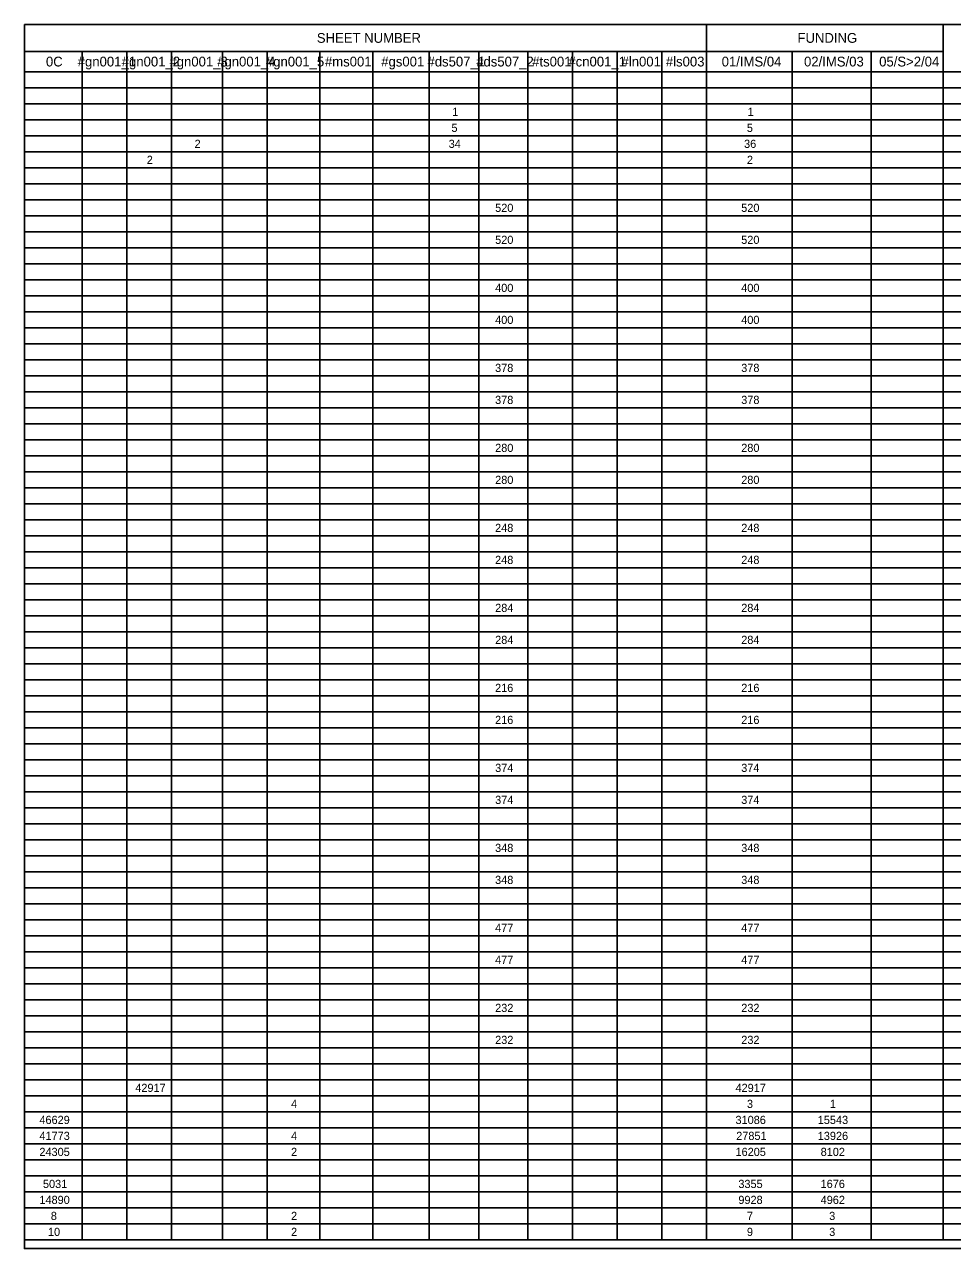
# Model space of a CAD drawing. Extents: x -542 to 295, y -281 to 32.
# Drawn here: x -416.36 to -400.45, y -70.59 to -49.59 of the extents above; entities that cross this region are included whole.
import ezdxf

# ---------------------------------------------------------------- set-up
doc = ezdxf.new("R2010")
doc.units = 0
for name, color, linetype in [('SC_Scratch1', 7, 'Continuous'), ('SH_Data', 7, 'Continuous'), ('SH_Text', 7, 'Continuous')]:
    doc.layers.add(name, color=color, linetype=linetype)

msp = doc.modelspace()

# ---------------------------------------------------------------- linework, layer by layer
at = {"layer": 'SC_Scratch1'}
msp.add_lwpolyline([(-416.359, -49.593), (-385.859, -49.593), (-385.859, -70.593), (-416.359, -70.593)], close=True, dxfattribs=at)
at = {"layer": 'SH_Data'}
for p, q in [((-416.359, -49.593), (-385.859, -49.593)), ((-416.359, -49.593), (-416.359, -50.68)), ((-404.663, -49.593), (-404.663, -70.444)), ((-400.608, -49.593), (-400.608, -70.444)), ((-416.359, -50.054), (-400.608, -50.054)), ((-415.369, -50.054), (-415.369, -70.444)), ((-414.603, -50.054), (-414.603, -70.444)), ((-413.836, -50.054), (-413.836, -70.444)), ((-412.964, -50.054), (-412.964, -70.444)), ((-412.198, -50.054), (-412.198, -70.444)), ((-411.293, -50.054), (-411.293, -70.444)), ((-410.388, -50.054), (-410.388, -70.444)), ((-409.42, -50.054), (-409.42, -70.444)), ((-408.569, -50.054), (-408.569, -70.444)), ((-407.728, -50.054), (-407.728, -70.444)), ((-406.962, -50.054), (-406.962, -70.444)), ((-406.195, -50.054), (-406.195, -70.444)), ((-405.429, -50.054), (-405.429, -70.444)), ((-403.194, -50.054), (-403.194, -70.444)), ((-401.843, -50.054), (-401.843, -70.444)), ((-416.359, -50.405), (-385.859, -50.405)), ((-416.359, -50.68), (-385.859, -50.68)), ((-416.359, -50.68), (-416.359, -50.954)), ((-416.359, -50.954), (-385.859, -50.954)), ((-416.359, -50.954), (-416.359, -70.444)), ((-416.359, -51.229), (-385.859, -51.229)), ((-416.359, -51.503), (-385.859, -51.503)), ((-416.359, -51.778), (-385.859, -51.778)), ((-416.359, -52.052), (-385.859, -52.052)), ((-416.359, -52.327), (-385.859, -52.327)), ((-416.359, -52.327), (-385.859, -52.327)), ((-416.359, -52.601), (-385.859, -52.601)), ((-416.359, -52.876), (-385.859, -52.876)), ((-416.359, -53.15), (-385.859, -53.15)), ((-416.359, -53.425), (-385.859, -53.425)), ((-416.359, -53.699), (-385.859, -53.699)), ((-416.359, -53.974), (-385.859, -53.974)), ((-416.359, -54.248), (-385.859, -54.248)), ((-416.359, -54.523), (-385.859, -54.523)), ((-416.359, -54.797), (-385.859, -54.797)), ((-416.359, -55.072), (-385.859, -55.072)), ((-416.359, -55.346), (-385.859, -55.346)), ((-416.359, -55.621), (-385.859, -55.621)), ((-416.359, -55.895), (-385.859, -55.895)), ((-416.359, -56.17), (-385.859, -56.17)), ((-416.359, -56.444), (-385.859, -56.444)), ((-416.359, -56.719), (-385.859, -56.719)), ((-416.359, -56.993), (-385.859, -56.993)), ((-416.359, -57.268), (-385.859, -57.268)), ((-416.359, -57.542), (-385.859, -57.542)), ((-416.359, -57.817), (-385.859, -57.817)), ((-416.359, -58.091), (-385.859, -58.091)), ((-416.359, -58.366), (-385.859, -58.366)), ((-416.359, -58.64), (-385.859, -58.64)), ((-416.359, -58.915), (-385.859, -58.915)), ((-416.359, -59.189), (-385.859, -59.189)), ((-416.359, -59.464), (-385.859, -59.464)), ((-416.359, -59.738), (-385.859, -59.738)), ((-416.359, -60.013), (-385.859, -60.013)), ((-416.359, -60.287), (-385.859, -60.287)), ((-416.359, -60.562), (-385.859, -60.562)), ((-416.359, -60.836), (-385.859, -60.836)), ((-416.359, -61.111), (-385.859, -61.111)), ((-416.359, -61.385), (-385.859, -61.385)), ((-416.359, -61.66), (-385.859, -61.66)), ((-416.359, -61.935), (-385.859, -61.935)), ((-416.359, -62.209), (-385.859, -62.209)), ((-416.359, -62.484), (-385.859, -62.484)), ((-416.359, -62.758), (-385.859, -62.758)), ((-416.359, -63.033), (-385.859, -63.033)), ((-416.359, -63.307), (-385.859, -63.307)), ((-416.359, -63.582), (-385.859, -63.582)), ((-416.359, -63.856), (-385.859, -63.856)), ((-416.359, -64.131), (-385.859, -64.131)), ((-416.359, -64.405), (-385.859, -64.405)), ((-416.359, -64.68), (-385.859, -64.68)), ((-416.359, -64.954), (-385.859, -64.954)), ((-416.359, -65.229), (-385.859, -65.229)), ((-416.359, -65.503), (-385.859, -65.503)), ((-416.359, -65.778), (-385.859, -65.778)), ((-416.359, -66.052), (-385.859, -66.052)), ((-416.359, -66.327), (-385.859, -66.327)), ((-416.359, -66.601), (-385.859, -66.601)), ((-416.359, -66.876), (-385.859, -66.876)), ((-416.359, -67.15), (-385.859, -67.15)), ((-416.359, -67.425), (-385.859, -67.425)), ((-416.359, -67.425), (-385.859, -67.425)), ((-416.359, -67.699), (-385.859, -67.699)), ((-416.359, -67.974), (-385.859, -67.974)), ((-416.359, -68.248), (-385.859, -68.248)), ((-416.359, -68.523), (-385.859, -68.523)), ((-416.359, -68.797), (-385.859, -68.797)), ((-416.359, -69.072), (-385.859, -69.072)), ((-416.359, -69.346), (-385.859, -69.346)), ((-416.359, -69.621), (-385.859, -69.621)), ((-416.359, -69.895), (-385.859, -69.895)), ((-416.359, -70.17), (-385.859, -70.17)), ((-416.359, -70.444), (-385.859, -70.444)), ((-416.359, -70.444), (-385.859, -70.444))]:
    msp.add_line(p, q, dxfattribs=at)

# ---------------------------------------------------------------- texts
at = {"layer": 'SH_Text'}
for s, height, p in [('SHEET NUMBER', 0.168, (-411.346, -49.907)), ('FUNDING', 0.168, (-403.105, -49.907)), ('0C', 0.168, (-415.991, -50.313)), ('#gn001_1', 0.168, (-415.446, -50.313)), ('#gn001_2', 0.168, (-414.691, -50.313)), ('#gn001_3', 0.168, (-413.873, -50.313)), ('#gn001_4', 0.168, (-413.055, -50.313)), ('#gn001_5', 0.168, (-412.219, -50.313)), ('#ms001', 0.168, (-411.207, -50.313)), ('#gs001', 0.168, (-410.242, -50.313)), ('#ds507_1', 0.168, (-409.449, -50.313)), ('#ds507_2', 0.168, (-408.614, -50.313)), ('#ts001', 0.168, (-407.654, -50.313)), ('#cn001_1', 0.168, (-407.033, -50.313)), ('#ln001', 0.168, (-406.122, -50.313)), ('#ls003', 0.168, (-405.362, -50.313)), ('01/IMS/04', 0.168, (-404.405, -50.313)), ('02/IMS/03', 0.168, (-402.993, -50.313)), ('05/S>2/04', 0.168, (-401.705, -50.313)), ('1', 0.14, (-409.026, -51.161)), ('1', 0.14, (-403.96, -51.161)), ('5', 0.14, (-409.038, -51.436)), ('5', 0.14, (-403.973, -51.436)), ('2', 0.14, (-413.443, -51.71)), ('34', 0.14, (-409.086, -51.71)), ('36', 0.14, (-404.021, -51.71)), ('2', 0.14, (-414.262, -51.985)), ('2', 0.14, (-403.972, -51.985)), ('520', 0.14, (-408.289, -52.808)), ('520', 0.14, (-404.07, -52.808)), ('520', 0.14, (-408.289, -53.357)), ('520', 0.14, (-404.07, -53.357)), ('400', 0.14, (-408.289, -54.181)), ('400', 0.14, (-404.07, -54.181)), ('400', 0.14, (-408.289, -54.73)), ('400', 0.14, (-404.07, -54.73)), ('378', 0.14, (-408.29, -55.554)), ('378', 0.14, (-404.07, -55.554)), ('378', 0.14, (-408.29, -56.103)), ('378', 0.14, (-404.07, -56.103)), ('280', 0.14, (-408.289, -56.926)), ('280', 0.14, (-404.07, -56.926)), ('280', 0.14, (-408.289, -57.475)), ('280', 0.14, (-404.07, -57.475)), ('248', 0.14, (-408.29, -58.299)), ('248', 0.14, (-404.07, -58.299)), ('248', 0.14, (-408.29, -58.848)), ('248', 0.14, (-404.07, -58.848)), ('284', 0.14, (-408.289, -59.671)), ('284', 0.14, (-404.07, -59.671)), ('284', 0.14, (-408.289, -60.22)), ('284', 0.14, (-404.07, -60.22)), ('216', 0.14, (-408.29, -61.044)), ('216', 0.14, (-404.07, -61.044)), ('216', 0.14, (-408.29, -61.593)), ('216', 0.14, (-404.07, -61.593)), ('374', 0.14, (-408.289, -62.416)), ('374', 0.14, (-404.07, -62.416)), ('374', 0.14, (-408.289, -62.965)), ('374', 0.14, (-404.07, -62.965)), ('348', 0.14, (-408.29, -63.789)), ('348', 0.14, (-404.07, -63.789)), ('348', 0.14, (-408.29, -64.338)), ('348', 0.14, (-404.07, -64.338)), ('477', 0.14, (-408.29, -65.161)), ('477', 0.14, (-404.07, -65.161)), ('477', 0.14, (-408.29, -65.71)), ('477', 0.14, (-404.07, -65.71)), ('232', 0.14, (-408.289, -66.534)), ('232', 0.14, (-404.069, -66.534)), ('232', 0.14, (-408.289, -67.083)), ('232', 0.14, (-404.069, -67.083)), ('42917', 0.14, (-414.459, -67.906)), ('42917', 0.14, (-404.168, -67.906)), ('3', 0.14, (-403.972, -68.181)), ('4', 0.14, (-411.788, -68.181)), ('1', 0.14, (-402.55, -68.181)), ('46629', 0.14, (-416.103, -68.456)), ('31086', 0.14, (-404.168, -68.456)), ('15543', 0.14, (-402.758, -68.456)), ('41773', 0.14, (-416.103, -68.73)), ('4', 0.14, (-411.788, -68.73)), ('27851', 0.14, (-404.156, -68.73)), ('13926', 0.14, (-402.758, -68.73)), ('24305', 0.14, (-416.103, -69.005)), ('2', 0.14, (-411.788, -69.005)), ('16205', 0.14, (-404.168, -69.005)), ('8102', 0.14, (-402.708, -69.005)), ('5031', 0.14, (-416.042, -69.554)), ('3355', 0.14, (-404.119, -69.554)), ('1676', 0.14, (-402.709, -69.554)), ('14890', 0.14, (-416.103, -69.828)), ('9928', 0.14, (-404.119, -69.828)), ('4962', 0.14, (-402.708, -69.828)), ('8', 0.14, (-415.907, -70.103)), ('2', 0.14, (-411.788, -70.103)), ('7', 0.14, (-403.972, -70.103)), ('3', 0.14, (-402.562, -70.103)), ('10', 0.14, (-415.956, -70.377)), ('2', 0.14, (-411.788, -70.377)), ('9', 0.14, (-403.972, -70.377)), ('3', 0.14, (-402.562, -70.377))]:
    msp.add_text(s, height=height, dxfattribs=at).set_placement(p)

doc.saveas('drawing.dxf')
